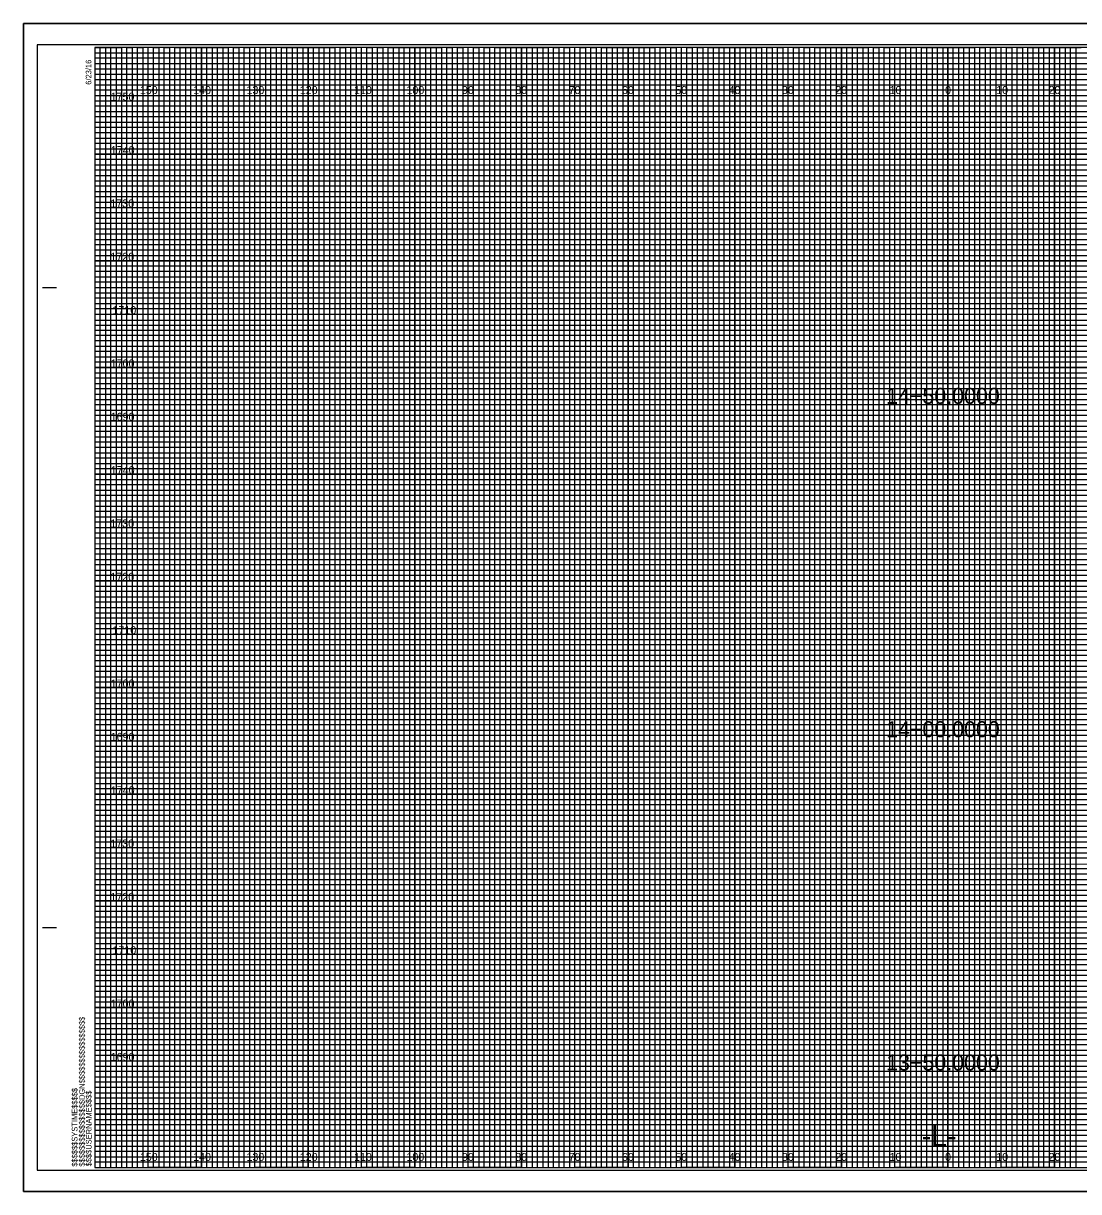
# Model space of a CAD drawing. Extents: x -419 to 4739, y -630 to 13534.
# Drawn here: x -13.4 to 184.5, y 655.5 to 874.5 of the extents above; entities that cross this region are included whole.
import ezdxf

# ---------------------------------------------------------------- set-up
doc = ezdxf.new("R2010")
doc.units = 0
for name, color, linetype in [('Old_Level_62', 7, 'Continuous'), ('Pattern 1', 7, 'Continuous'), ('Pattern 18', 7, 'Continuous'), ('Pattern 4', 7, 'Continuous'), ('Pattern 5', 7, 'Continuous'), ('Prop Dimension', 7, 'Continuous'), ('Prop Horizontal Alignment', 7, 'Continuous'), ('Prop PHM White Shape', 7, 'Continuous'), ('Raster_Level_0', 7, 'Continuous'), ('Scratch_Level_0', 7, 'Continuous'), ('Scratch_Level_2', 7, 'Continuous'), ('Scratch_Level_3', 7, 'Continuous'), ('Scratch_Level_5', 7, 'Continuous')]:
    doc.layers.add(name, color=color, linetype=linetype)

msp = doc.modelspace()

# ---------------------------------------------------------------- linework, layer by layer
at = {"layer": 'Old_Level_62'}
for p, q in [((-9.8, 825), (-7.3, 825)), ((-9.7, 825), (-7.2, 825)), ((-9.8, 705), (-7.3, 705)), ((-9.7, 705), (-7.2, 705)), ((0, 660), (0, 660)), ((0, 660), (0, 660)), ((0, 660), (0, 660)), ((0, 660), (0, 660)), ((0, 660), (0, 660)), ((0, 660), (0, 660)), ((0, 660), (0, 660))]:
    msp.add_line(p, q, dxfattribs=at)
msp.add_lwpolyline([(320, 870), (0, 870), (0, 660), (320, 660)], close=True, dxfattribs=at)
at = {"layer": 'Pattern 18'}
for points in [[(-13.4, 655.5), (323.3, 655.5), (323.3, 874.5), (-13.4, 874.5)], [(-13.4, 874.5), (323.3, 874.5), (323.3, 655.5), (-13.4, 655.5)]]:
    msp.add_lwpolyline(points, close=True, dxfattribs=at)
at = {"layer": 'Pattern 4'}
for p, q in [((0, 869), (260, 869)), ((260, 867.98), (0, 867.98)), ((0, 867.98), (0, 867)), ((0, 867), (260, 867)), ((260, 865.89), (0, 865.89)), ((0, 865.89), (0, 864)), ((0, 864), (320, 864))]:
    msp.add_line(p, q, dxfattribs=at)
for points in [[(0, 863), (270, 863), (320, 863), (320, 862), (0, 862)], [(0, 861), (320, 861), (320, 859), (0, 859)], [(0, 858), (320, 858), (320, 857), (0, 856.98)], [(0, 856), (320, 856), (320, 854), (0, 854)], [(0, 853), (320, 853), (320, 852), (0, 852)], [(0, 851), (320, 851), (320, 849), (0, 849)], [(0, 848), (320, 848), (320, 847), (0, 847)], [(0, 846), (320, 846), (320, 844), (0, 844)], [(0, 843), (320, 843), (320, 842), (0, 842)], [(0, 841), (320, 841), (320, 839), (0, 839)], [(0, 838), (320, 838), (320, 837), (0, 837)], [(0, 836), (320, 836), (320, 833.95), (320, 833), (320, 832), (0, 832)], [(0, 834), (320, 834), (320, 833), (0, 833)], [(0, 831), (320, 831), (320, 829), (0, 829.03)], [(0, 829.03), (320, 829), (320, 828), (0, 828)], [(0, 827), (320, 827), (320, 826), (0, 826)], [(0, 824), (320, 824), (320, 823), (0, 823)], [(0, 822), (320, 822), (320, 821), (0, 821)], [(-0.07, 818.89), (320, 818.89), (320, 817.88), (-0.07, 817.88)], [(0, 817), (320, 817), (320, 816), (0, 816)], [(0, 814), (320, 814), (320, 813), (0, 813)], [(0, 812), (320, 812), (320, 811), (0, 811)], [(0, 809), (320, 809), (320, 808), (0, 808)], [(0, 807), (320, 807), (320, 806), (0, 806)], [(0, 804), (320, 804), (320, 803), (0, 803)], [(0, 802), (320, 802), (320, 801), (0, 801)], [(0, 799), (320, 799), (319.99, 797.98), (0, 798)], [(0, 797), (320, 797), (320, 796), (0, 796)], [(0, 794), (320, 794), (320, 793), (0, 793)], [(0, 792), (320, 792), (320, 791), (0, 791)], [(0, 789), (320, 789), (320, 788), (0, 788)], [(0, 787), (320, 787), (320, 786), (0, 786)], [(0, 784), (320, 784), (320, 783), (0, 783)], [(0, 782), (320, 782), (320, 781), (0, 781)], [(0, 779), (320, 779), (320, 778), (0, 778)], [(0, 776.99), (320.07, 776.91), (320, 776), (0, 776)], [(0, 774), (320, 774), (320, 773), (0, 773)], [(0, 772), (320, 772), (320, 771), (0, 771)], [(0, 769), (320, 769), (320, 768), (0, 768)], [(0, 767), (320, 767), (320, 766), (0, 766)], [(0, 764), (320, 764), (320, 763), (0, 763)], [(0, 762), (320, 762), (320, 761), (0, 761)], [(0, 759), (320, 759), (320, 758), (0, 758)], [(0, 757), (320, 757), (320, 756), (0, 756)], [(0, 754), (320, 754), (320, 753), (0, 753)], [(0, 752), (320, 752), (320, 751), (0, 751)], [(0, 749), (320, 749), (320, 748), (0, 748)], [(0, 747), (320, 747), (320, 746), (0, 746)], [(0, 744), (320, 744), (320, 743), (0, 743)], [(0, 742), (320, 742), (320, 741), (0, 741)], [(0, 739), (320, 739), (319.99, 737.98), (0, 738)], [(0, 737), (320, 737), (320, 736), (0, 736)], [(0, 734), (320, 734), (320, 733), (0, 733)], [(0, 732), (320, 732), (320, 731), (0, 731)], [(0, 729), (320, 729), (320, 728), (0, 728)], [(0, 727), (320, 727), (320, 726), (0, 726)], [(0, 724), (320, 724), (320, 723), (0, 723)], [(0, 722), (320, 722), (320, 721), (0, 721)], [(0, 719), (320, 719), (320, 718), (0, 718)], [(0, 716.99), (320.07, 716.91), (320, 716), (0, 716)], [(0, 714), (320, 714), (320, 713), (0, 713)], [(0, 712), (320, 712), (320, 711), (0, 711)], [(0, 709), (320, 709), (320, 708), (0, 708)], [(0, 707), (320, 707), (320, 706), (0, 706)], [(0, 704), (320, 704), (320, 703), (0, 703)], [(0, 702), (320, 702), (320, 701), (0, 701)], [(0, 699), (320, 699), (320, 698), (0, 698)], [(0, 697), (320, 697), (320, 696), (0, 696)], [(0, 694), (320, 694), (320, 693), (0, 693)], [(0, 692), (320, 692), (320, 691), (0, 691)], [(0, 689), (320, 689), (320, 688), (0, 688)], [(0, 687), (320, 687), (320, 686), (0, 686)], [(0, 684), (320, 684), (320, 683), (0, 683)], [(0, 682), (320, 682), (320, 681), (0, 681)], [(0, 679), (320, 679), (320, 678), (0, 678)], [(0, 677), (320, 677), (320, 676), (0, 676)], [(0, 674), (320, 674), (320, 673), (0, 673)], [(0, 672), (320, 672), (320, 671), (0, 671)], [(0, 669), (320, 669), (320, 668), (0, 668)], [(0, 667), (320, 667), (320, 666), (0, 666)], [(0, 664), (320, 664), (320, 663), (0, 663)], [(0, 662), (320, 662), (320, 661), (0, 661)]]:
    msp.add_lwpolyline(points, dxfattribs=at)
at = {"layer": 'Pattern 5'}
for p, q in [((323.3, 874.5), (-13.4, 874.5)), ((-13.4, 874.5), (-13.4, 655.5)), ((-13.4, 655.5), (323.3, 655.5))]:
    msp.add_line(p, q, dxfattribs=at)
at = {"layer": 'Prop Dimension'}
for points in [[(0, 660), (1, 660), (1, 870), (2, 870), (2, 660)], [(2, 660), (3, 660), (3, 870), (4, 870), (4, 660)], [(5, 660), (6, 660), (6, 870), (7, 870), (7, 660)], [(7, 660), (8, 660), (8, 870), (9, 870), (9, 660)], [(10, 660), (11, 660), (11, 870), (12, 870), (12, 660)], [(12, 660), (13, 660), (13, 870), (14, 870), (14, 660)], [(15, 660), (16, 660), (16, 870), (17, 870), (17, 660)], [(17, 660), (18, 660), (18, 870), (19, 870), (19, 660)], [(20, 660), (21, 660), (21, 870), (22, 870), (22, 660)], [(22, 660), (23, 660), (23, 870), (24, 870), (24, 660)], [(25, 660), (26, 660), (26, 870), (27, 870), (27, 660)], [(27, 660), (28, 660), (28, 870), (29, 870), (29, 660)], [(30, 660), (31, 660), (31, 870), (32, 870), (32, 660)], [(32, 660), (33, 660), (33, 870), (34, 870), (34, 660)], [(35, 660), (36, 660), (36, 870), (37, 870), (37, 660)], [(37, 660), (38, 660), (38, 870), (39, 870), (39, 660)], [(40, 660), (41, 660), (41, 870), (42, 870), (42, 660)], [(42, 660), (43, 660), (43, 870), (44, 870), (44, 660)], [(45, 660), (46, 660), (46, 870), (47, 870), (47, 660)], [(47, 660), (48, 660), (48, 870), (49, 870), (49, 660)], [(50, 660), (51, 660), (51, 870), (52, 870), (52, 660)], [(52, 660), (53, 660), (53, 870), (54, 870), (54, 660)], [(55, 660), (56, 660), (56, 870), (57, 870), (57, 660)], [(57, 660), (58, 660), (58, 870), (59, 870), (59, 660)], [(60, 660), (61, 660), (61, 870), (62, 870), (62, 660)], [(62, 660), (63, 660), (63, 870), (64, 870), (64, 660)], [(65, 660), (66, 660), (66, 870), (67, 870), (67, 660)], [(67, 660), (68, 660), (68, 870), (69, 870), (69, 660)], [(70, 660), (71, 660), (71, 870), (72, 870), (72, 660)], [(72, 660), (73, 660), (73, 870), (74, 870), (74, 660)], [(75, 660), (76, 660), (76, 870), (77, 870), (77, 660)], [(77, 660), (78, 660), (78, 870), (79, 870), (79, 660)], [(80, 660), (81, 660), (81, 870), (82, 870), (82, 660)], [(82, 660), (83, 660), (83, 870), (84, 870), (84, 660)], [(85, 660), (86, 660), (86, 870), (87, 870), (87, 660)], [(87, 660), (88, 660), (88, 870), (89, 870), (89, 660)], [(90, 660), (91, 660), (91, 870), (92, 870), (92, 660)], [(92, 660), (93, 660), (93, 870), (94, 870), (94, 660)], [(95, 660), (96, 660), (96, 870), (97, 870), (97, 660)], [(97, 660), (98, 660), (98, 870), (99, 870), (99, 660)], [(100, 660), (101, 660), (101, 870), (102, 870), (102, 660)], [(102, 660), (103, 660), (103, 870), (104, 870), (104, 660)], [(105, 660), (106, 660), (106, 870), (107, 870), (107, 660)], [(107, 660), (108, 660), (108, 870), (109, 870), (109, 660)], [(110, 660), (111, 660), (111, 870), (112, 870), (112, 660)], [(112, 660), (113, 660), (113, 870), (114, 870), (114, 660)], [(115, 660), (116, 660), (116, 870), (117, 870), (117, 660)], [(117, 660), (118, 660), (118, 870), (119, 870), (119, 660)], [(120, 660), (121, 660), (121, 870), (122, 870), (122, 660)], [(122, 660), (123, 660), (123, 870), (124, 870), (124, 660)], [(125, 660), (126, 660), (126, 870), (127, 870), (127, 660)], [(127, 660), (128, 660), (128, 870), (129, 870), (129, 660)], [(130, 660), (131, 660), (131, 870), (132, 870), (132, 660)], [(132, 660), (133, 660), (133, 870), (134, 870), (134, 660)], [(135, 660), (136, 660), (136, 870), (137, 870), (137, 660)], [(137, 660), (138, 660), (138, 870), (139, 870), (139, 660)], [(140, 660), (141, 660), (141, 870), (142, 870), (142, 660)], [(142, 660), (143, 660), (143, 870), (144, 870), (144, 660)], [(145, 660), (146, 660), (146, 870), (147, 870), (147, 660)], [(147, 660), (148, 660), (148, 870), (149, 870), (149, 660)], [(150, 660), (151, 660), (151, 870), (152, 870), (152, 660)], [(152, 660), (153, 660), (153, 870), (154, 870), (154, 660)], [(155, 660), (156, 660), (156, 870), (157, 870), (157, 660)], [(157, 660), (158, 660), (158, 870), (159, 870), (159, 660)], [(160, 660), (161, 660), (161, 870), (162, 870), (162, 660)], [(162, 660), (163, 660), (163, 870), (164, 870), (164, 660)], [(165, 660), (166, 660), (166, 870), (167, 870), (167, 660)], [(167, 660), (168, 660), (168, 870), (169, 870), (169, 660)], [(170, 660), (171, 660), (171, 870), (172, 870), (172, 660)], [(172, 660), (173, 660), (173, 870), (174, 870), (174, 660)], [(175, 660), (176, 660), (176, 870), (177, 870), (177, 660)], [(177, 660), (178, 660), (178, 870), (179, 870), (179, 660)], [(180, 660), (181, 660), (181, 870), (182, 870), (182, 660)], [(182, 660), (183, 660), (183, 870), (184, 870), (184, 660)]]:
    msp.add_lwpolyline(points, dxfattribs=at)
at = {"layer": 'Prop Horizontal Alignment'}
for points in [[(0, 870), (5, 870), (5, 660), (15, 660), (15, 870), (25, 870), (25, 660), (35, 660), (35, 870), (45, 870), (45, 660), (55, 660), (55, 870), (65, 870), (65, 660), (75, 660), (75, 870), (85, 870), (85, 660), (95, 660), (95, 870), (105, 870), (105, 660), (115, 660), (115, 870), (125, 870), (125, 660), (135, 660), (135, 870), (145, 870), (145, 660), (155, 660), (155, 870), (165, 870), (165, 660), (175, 660), (175, 870), (185, 870)], [(0, 865), (275, 865)], [(0, 845), (320, 845), (320, 855), (0, 855)], [(0, 825), (320, 825), (320, 835), (0, 835)], [(0, 805), (320, 805), (320, 815), (0, 815)], [(0, 785), (320, 785), (320, 795), (0, 795)], [(0, 765), (320, 765), (320, 775), (0, 775)], [(0, 745), (320, 745), (320, 755), (0, 755)], [(0, 725), (320, 725), (320, 735), (0, 735)], [(0, 705), (320, 705), (320, 715), (0, 715)], [(0, 685), (320, 685), (320, 695), (0, 695)], [(0, 665), (320, 665), (320, 675), (0, 675)]]:
    msp.add_lwpolyline(points, dxfattribs=at)
at = {"layer": 'Scratch_Level_0'}
for p, q in [((10, 660), (10, 870)), ((20, 660), (20, 870)), ((30, 660), (30, 870)), ((40, 660), (40, 870)), ((50, 660), (50, 870)), ((60, 660), (60, 870)), ((70, 660), (70, 870)), ((80, 660), (80, 870)), ((90, 660), (90, 870)), ((100, 660), (100, 870)), ((110, 660), (110, 870)), ((120, 660), (120, 870)), ((130, 660), (130, 870)), ((140, 660), (140, 870)), ((150, 660), (150, 870)), ((160, 660), (160, 870)), ((170, 660), (170, 870)), ((180, 660), (180, 870)), ((0, 860), (320, 860)), ((0, 850), (320, 850)), ((0, 840), (320, 840)), ((0, 830), (320, 830)), ((0, 820), (320, 820)), ((0, 810), (320, 810)), ((0, 800), (320, 800)), ((0, 790), (320, 790)), ((0, 780), (320, 780)), ((0, 770), (320, 770)), ((0, 760), (320, 760)), ((0, 750), (320, 750)), ((0, 740), (320, 740)), ((0, 730), (320, 730)), ((0, 720), (320, 720)), ((0, 710), (320, 710)), ((0, 700), (320, 700)), ((0, 690), (320, 690)), ((0, 680), (320, 680)), ((0, 670), (320, 670))]:
    msp.add_line(p, q, dxfattribs=at)
at = {"layer": 'Scratch_Level_3'}
for p, q in [((10, 870), (0, 870)), ((10, 660), (10, 870)), ((30, 870), (20, 870)), ((20, 870), (20, 660)), ((30, 660), (30, 870)), ((50, 870), (40, 870)), ((40, 870), (40, 660)), ((50, 660), (50, 870)), ((70, 870), (60, 870)), ((60, 870), (60, 660)), ((70, 660), (70, 870)), ((90, 870), (80, 870)), ((80, 870), (80, 660)), ((90, 660), (90, 870)), ((110, 870), (100, 870)), ((100, 870), (100, 660)), ((110, 660), (110, 870)), ((130, 870), (120, 870)), ((120, 870), (120, 660)), ((130, 660), (130, 870)), ((150, 870), (140, 870)), ((140, 870), (140, 660)), ((150, 660), (150, 870)), ((170, 870), (160, 870)), ((160, 870), (160, 660)), ((170, 660), (170, 870)), ((190, 870), (180, 870)), ((180, 870), (180, 660)), ((20, 660), (10, 660)), ((40, 660), (30, 660)), ((60, 660), (50, 660)), ((80, 660), (70, 660)), ((100, 660), (90, 660)), ((120, 660), (110, 660)), ((140, 660), (130, 660)), ((160, 660), (150, 660)), ((180, 660), (170, 660))]:
    msp.add_line(p, q, dxfattribs=at)
for points in [[(0, 860), (320, 860), (320, 850), (0, 850)], [(0, 840), (320, 840), (320, 830), (0, 830)], [(0, 820), (320, 820), (320, 810), (0, 810)], [(0, 800), (320, 800), (320, 790), (0, 790)], [(0, 780), (320, 780), (320, 770), (0, 770)], [(0, 760), (320, 760), (320, 750), (0, 750)], [(0, 740), (320, 740), (320, 730), (0, 730)], [(0, 720), (320, 720), (320, 710), (0, 710)], [(0, 700), (320, 700), (320, 690), (0, 690)], [(0, 680), (320, 680), (320, 670), (0, 670)]]:
    msp.add_lwpolyline(points, dxfattribs=at)
at = {"layer": 'Scratch_Level_5'}
msp.add_lwpolyline([(-10.8, 659.5), (322.4, 659.5), (322.4, 870.5), (-10.8, 870.5)], close=True, dxfattribs=at)

# ---------------------------------------------------------------- texts
at = {"layer": 'Old_Level_62'}
for s, p in [('6/23/16', (-0.65, 863)), ('$$$$$$$$$$$$$$$$DGN$$$$$$$$$$$$$$$$', (-1.88, 660.18)), ('$$$$$$SYSTIME$$$$$', (-3.26, 660.18)), ('$$$$USERNAME$$$$', (-0.62, 660.23))]:
    msp.add_text(s, height=1.05, rotation=90, dxfattribs=at).set_placement(p)
at = {"layer": 'Pattern 1'}
for s, p in [('1750', (2.96, 860)), ('1740', (3, 850)), ('1730', (2.92, 840)), ('1720', (2.93, 830)), ('1710', (3.31, 820)), ('1700', (2.98, 810)), ('1690', (2.97, 800)), ('1740', (3, 790)), ('1730', (2.92, 780)), ('1720', (2.93, 770)), ('1710', (3.31, 760)), ('1700', (2.98, 750)), ('1690', (2.97, 740)), ('1740', (3, 730)), ('1730', (2.92, 720)), ('1720', (2.93, 710)), ('1710', (3.31, 700)), ('1700', (2.98, 690)), ('1690', (2.97, 680))]:
    msp.add_text(s, height=1.5, dxfattribs=at).set_placement(p)
at = {"layer": 'Prop PHM White Shape'}
msp.add_text('-L-', height=4, dxfattribs=at).set_placement((155.06, 664))
at = {"layer": 'Raster_Level_0'}
for s, p in [('150', (8.44, 861.25)), ('140', (18.44, 861.25)), ('130', (28.44, 861.25)), ('120', (38.44, 861.25)), ('110', (48.62, 861.25)), ('100', (58.44, 861.25)), ('90', (68.86, 861.25)), ('80', (78.86, 861.25)), ('70', (88.86, 861.25)), ('60', (98.86, 861.25)), ('50', (108.86, 861.25)), ('40', (118.86, 861.25)), ('30', (128.86, 861.25)), ('20', (138.86, 861.25)), ('10', (149.04, 861.25)), ('0', (159.45, 861.25)), ('0', (159.45, 861.25)), ('10', (169.04, 861.25)), ('20', (178.86, 861.25)), ('150', (8.44, 661.25)), ('140', (18.44, 661.25)), ('130', (28.44, 661.25)), ('120', (38.44, 661.25)), ('110', (48.62, 661.25)), ('100', (58.44, 661.25)), ('90', (68.86, 661.25)), ('80', (78.86, 661.25)), ('70', (88.86, 661.25)), ('60', (98.86, 661.25)), ('50', (108.86, 661.25)), ('40', (118.86, 661.25)), ('30', (128.86, 661.25)), ('20', (138.86, 661.25)), ('10', (149.04, 661.25)), ('0', (159.45, 661.25)), ('0', (159.45, 661.25)), ('10', (169.04, 661.25)), ('20', (178.86, 661.25))]:
    msp.add_text(s, height=1.5, dxfattribs=at).set_placement(p)
at = {"layer": 'Scratch_Level_2'}
for s, p in [('14+50.0000', (148.4, 803.17)), ('14+00.0000', (148.4, 740.68)), ('13+50.0000', (148.4, 678.21))]:
    msp.add_text(s, height=3, dxfattribs=at).set_placement(p)

doc.saveas('drawing.dxf')
